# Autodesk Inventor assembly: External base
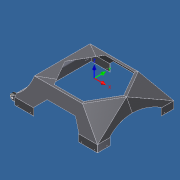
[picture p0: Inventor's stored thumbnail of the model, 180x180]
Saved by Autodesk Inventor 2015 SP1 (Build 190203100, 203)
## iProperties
Category: Mechanical Engineering Drawing and Design - CADD
Manager: Fábio Ricardo de Oliveira Souza
Company: SENAI - Serviço Nacional de Aprendizagem Industrial
Created: 2011-06
Part Number: External base
Document SubType Name: Weldment
Designer: Guilherme Augusto Franco de Souza
Engineer: George Geraldo de Oliveia Silva
Authority: Fábio Ricardo de Oliveira Soza
Weld Material: Welded Stainless Steel, 440C
Mass: 4109.69 g
Surface Area: 9281.65 cm^2
Volume: 523.539 cm^3
Density: 7.84983 g/cm^3
Description: Sub-assembly
Subject: WorldSkill 2011 - London, England
Author: Guilherme Augusto Franco de Souza
Revision Number: 00
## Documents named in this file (4)
- E:\Visitor Experience Project\WSI2015 - Visitor Experience Project\#46- Sheet Metal Technology\01- 3D Models\Outodoor Heater\2- Assemblies\External base.iam
- E:\Visitor Experience Project\WSI2015 - Visitor Experience Project\#46- Sheet Metal Technology\01- 3D Models\Outodoor Heater\1- Parts\External base - Rear.ipt
- E:\Visitor Experience Project\WSI2015 - Visitor Experience Project\#46- Sheet Metal Technology\01- 3D Models\Outodoor Heater\1- Parts\External base - Left.ipt
- E:\Visitor Experience Project\WSI2015 - Visitor Experience Project\#46- Sheet Metal Technology\01- 3D Models\Outodoor Heater\1- Parts\External base - Right.ipt
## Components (3 placed, 3 different names)
1. External base - Rear:1 — Flush:20, Flush:23
2. External base - Right:1 — Flush:20
3. External base - Left:1 — Flush:23
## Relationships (2: Flush 2)
- Flush:20: External base - Rear:1 ↔ External base - Right:1
- Flush:23: External base - Rear:1 ↔ External base - Left:1
